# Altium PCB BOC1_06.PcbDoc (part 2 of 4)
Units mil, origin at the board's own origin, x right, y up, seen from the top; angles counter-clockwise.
Board outline 7900 x 6500 mil, 2 copper layers (Top Layer, Bottom Layer); 312 components, 413 nets, 1710 pads, 368 vias.
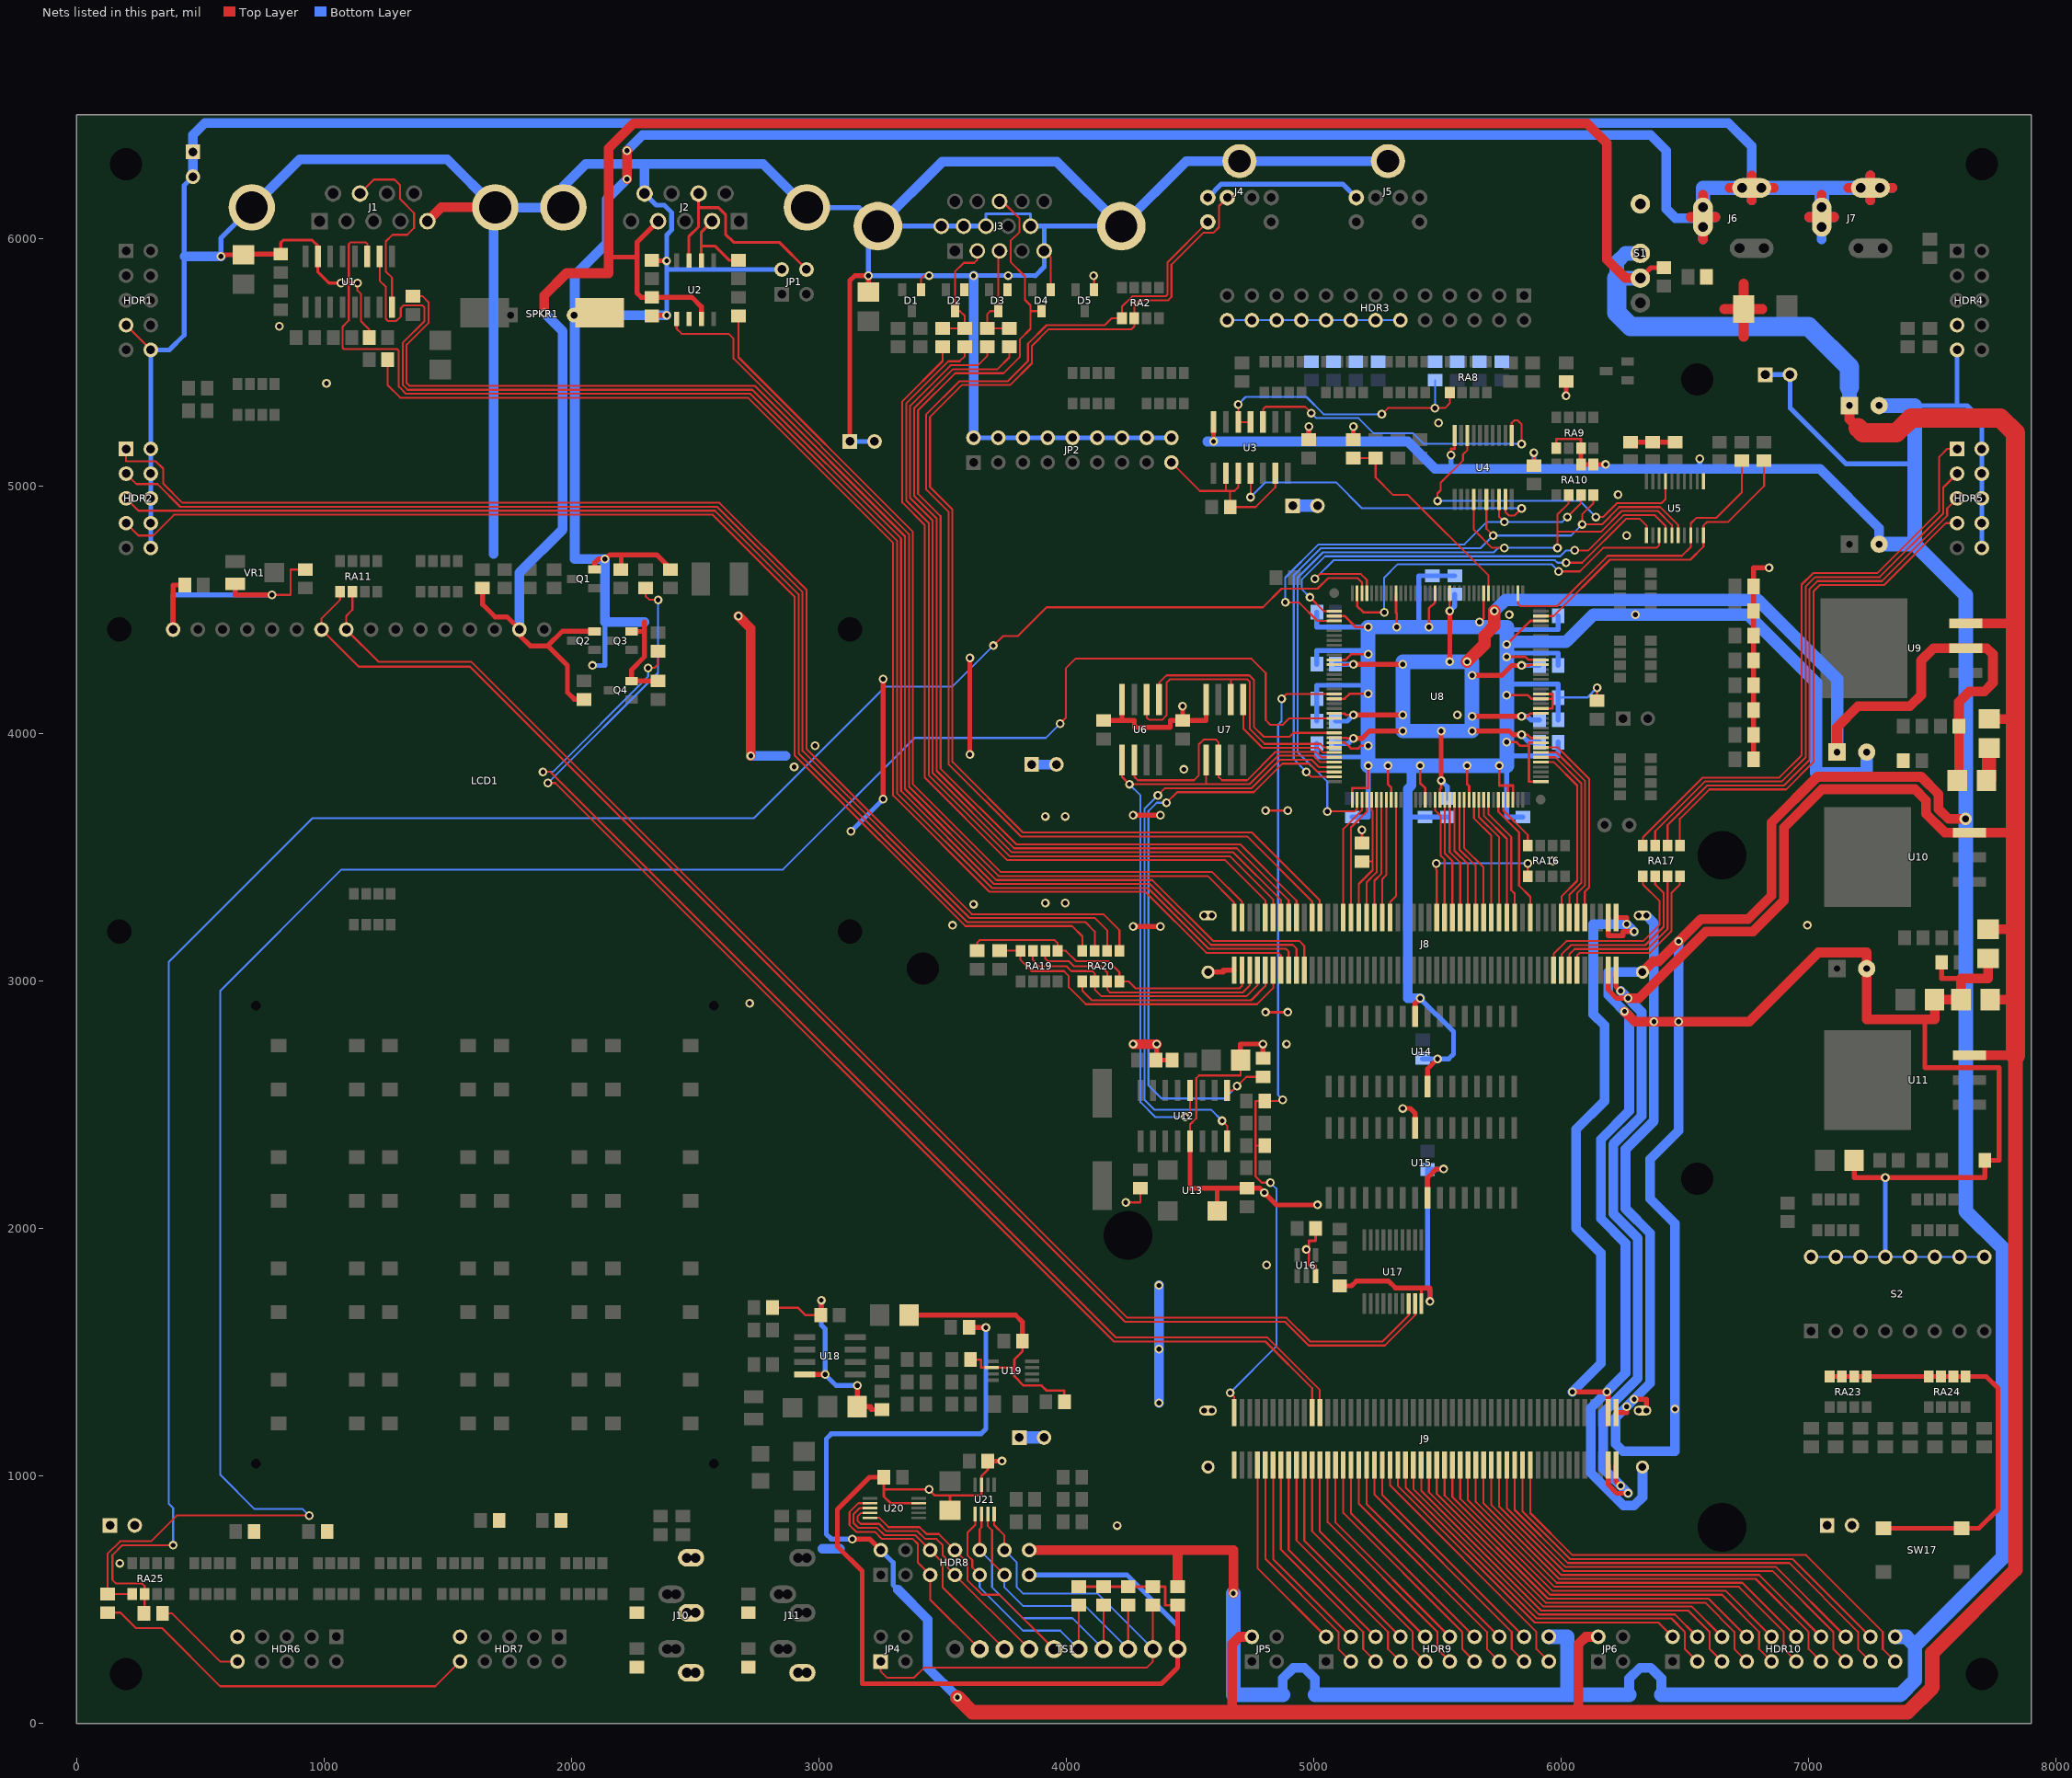
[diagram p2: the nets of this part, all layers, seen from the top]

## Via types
v1: diameter 35.43, hole 19.68, Top Layer to Bottom Layer, 194 vias
v2: diameter 35.43, hole 19.68, Top Layer to Bottom Layer, tented both sides, 169 vias
v3: diameter 50, hole 27.56, Top Layer to Bottom Layer, 5 vias

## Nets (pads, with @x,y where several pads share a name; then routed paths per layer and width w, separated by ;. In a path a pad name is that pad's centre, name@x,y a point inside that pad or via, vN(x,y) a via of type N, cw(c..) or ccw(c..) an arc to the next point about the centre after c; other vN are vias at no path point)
1V8: C21.1 C23.1 C58.1 C62.1 C63.1 C66.1 C67.1 C68.1 C69.1 C71.1 R42.1 U8.19 U8.46 U8.51 U8.61 U8.88 U8.120 U8.130 U8.135 U9.2 | length 7663.7
  Top Layer w9.84: U8.135@5082.68,3982.68 5132.32,3982.68 5135,3980 v1(5160,3980) ; U8.130@5082.68,4081.1 5123.9,4081.1 5130,4075 v1(5160,4075) ; U8.120@5082.68,4277.95 5132.95,4277.95 5135,4280 v1(5160,4280) ; U8.19@5509.84,3732.68 5509.84,3774.84 5515,3780 v1(5515,3810) ; v1@5549.21,4495.79 U8.88@5549.21,4567.32 ; v1(5840,3995) 5865,3995 5877.32,3982.68 U8.46@5917.32,3982.68 ; v1(5840,4070) 5865,4070 5876.1,4081.1 U8.51@5917.32,4081.1 ; v1(5840,4275) 5870,4275 5872.95,4277.95 U8.61@5917.32,4277.95
  Top Layer w19.68: v1(5160,3980) 5195,3980 5225,4010 v1(5360,4010) ; v1(5160,4075) v1(5360,4075) ; v1(5160,4280) v1(5360,4280) ; v1(5515,3810) v1(5515,4010) ; v1(5550,4290) v1(5550,4495) ; v1(5640,4010) 5790,4010 5805,3995 v1(5840,3995) ; v1(5640,4070) v1(5840,4070) ; v1(5640,4235) 5760,4235 5800,4275 v1(5840,4275)
  Top Layer w35.43: C23.1@7600.95,3810 7607.4,3816.46 R42.1@7607.4,4030
  Top Layer w39.37: C21.1@7115,3925 7115,4025 7200,4110 7410,4110 7455,4155 7455,4295 7505,4345 7720,4345 7745,4320 7745,4205 7710,4170 7650,4170 7607.4,4127.4 R42.1@7607.4,4030
  Top Layer w50: v1(5620,4290) 5690,4360 5690,4395 5730,4435 v1(5730,4495)
  Bottom Layer w19.68: C69.1@5087.4,3960 5140,3960 v1(5160,3980) ; C67.1@5087.4,4050 5135,4050 v1(5160,4075) ; C63.1@5087.4,4280 v1(5160,4280) ; v1(5515,3810) 5540,3785 C71.1@5540,3737.4 ; v1(5550,4495) 5570,4515 C58.1@5570,4562.6 ; v1(5840,3995) 5870,3965 C68.1@5912.6,3965 ; v1(5840,4070) 5862,4070 5877,4055 C66.1@5912.6,4055 ; v1(5840,4275) C62.1@5912.6,4275
  Bottom Layer w50: v1(5730,4495) 5775,4540 6795,4540 7115,4220 C21.1@7115,3925
  Bottom Layer w59.06: v1(5360,4010) 5360,4290 5640,4290 v1(5640,4010) v1(5360,4010)
5V: C4.1 C15.1 C22.1 C26.1 C27.1 HDR8.2 J2.4 J8.97 J8.99 J9.97 J9.99 JP5.2 JP6.2 LCD1.15 Q2.2 R5.1 R30.1 R38.1 R61.1 S1.1 S1.2 U2.3 U9.3 U10.3 U11.3 | length 29328.4
  Top Layer w19.68: R30.1@1641.48,4583.6 1641.48,4521.1 1691.57,4471 1740.43,4471 LCD1.15@1790.57,4420.86 ; LCD1.15@1791.54,4418.46 1791.54,4396.04 1833.57,4354 1904.57,4354 ; R38.1@2051.47,4138.6 2010.98,4138.6 1983.57,4166 1983.57,4275 1904.57,4354 ; Q2.2@2094.88,4413.4 1963.98,4413.4 1904.57,4354 ; 2150,5925 2265,5925 ; J2.4@2350.24,6070.08 2265,5984.84 2265,5780 2282.6,5762.4 2487.6,5762.4 2525,5725 U2.3@2525,5675 ; v1(3135,745) 3205,745 HDR8.2@3250,700 ; R61.1@3607.4,1600 v1(3675,1600) ; J9.97@6190.16,1043.7 6190.16,964.84 6225,930 v1(6270,930) ; J8.97@6190.16,3043.7 6190.16,2964.84 6225,2930 v1(6270,2930) ; J9.99@6221.65,1043.7 6221.65,978.35 v1(6240,960) ; J8.99@6221.65,3043.7 6221.65,2978.35 v1(6240,2960) ; S1.2@6320,5840 6362.4,5882.4 R5.1@6415,5882.4
  Top Layer w39.37: v2(1890,5700) 1890,5770 1980,5860 2150,5860 2150,6365 2250,6465 6105,6465 6185,6385 6185,5915 6260,5840 S1.2@6320,5840 ; 4670,45 4670,320 4700,350 JP5.2@4750,350 ; 6070,45 6070,320 6100,350 JP6.2@6150,350 ; v1(6270,2930) 6315,2930 6585,3200 6775,3200 6900,3325 6900,3620 7055,3775 7430,3775 7475,3730 7475,3675 7550,3600 7836,3600 ; C15.1@7165,5325 7165,5270 7200,5235 ; U9.3@7635,4445 7836,4445 ; U11.3@7650,2700 7836,2700 ; C27.1@7725,3209.05 7836,3209.05 ; C22.1@7730,4059.05 7836,4059.05 ; C26.1@7734.05,2925 7836,2925
  Top Layer w59.06: v1(3560,105) 3620,45 7400,45 7500,145 7500,285 7836,621 7836,2700
  Top Layer w78.74: 7200,5235 7220,5215 7355,5215 7415,5275 7775,5275 7836,5214 7836,2700
  Bottom Layer w19.68: v1(3135,745) 3050,745 3030,765 3030,1150 3050,1170 3655,1170 3675,1190 v1(3675,1600) ; HDR8.2@3250,700 3300,650 3300,560 3320,540
  Bottom Layer w39.37: LCD1.15@1790,4420 1790,4650 1965,4825 1965,5625 v2(1890,5700) ; 3320,540 3440,420 3440,225 v1(3560,105) ; v1(6240,2960) 6325,2875 6325,2455 6210,2340 6210,2060 6310,1960 6310,1395 6170,1255 6170,1030 v1(6270,930)
  Bottom Layer w59.06: S1.2@6320,5840 6225,5840 6225,5905 6260,5940 S1.1@6320,5940 ; C15.1@7165,5325 7165,5400
  Bottom Layer w78.74: 6225,5840 6225,5700 6280,5645 7000,5645 7165,5480 7165,5400
AGND: C36.2 C37.1 C38.2 C39.2 C41.2 C42.2 C44.2 C47.2 C48.2 C49.2 C50.2 C51.2 C52.2 C53.2 C54.2 C55.2 C56.2 C57.2 HDR8.13 J10.1 J10.1A J10.1B J10.3 J10.3A J10.3B J10.5 J10.5A J10.5B J11.1 J11.1A J11.1B R65.1 R80.2 TS1.10 U18.4 U19.2 U20.4 U21.7 | length 6959.1
  Top Layer w9.84: C36.2@2812.4,1680 2915,1680 2945,1650 C37.1@3010,1650 ; 3262.6,945 v1(3445,945) 3469,921 3657.2,921 3657.2,999.2 3682.4,1024.4 C49.2@3682.4,1060 ; C47.2@3262.6,995 3262.6,917.4 3290.32,889.68 U20.4@3403.43,889.68 ; C48.2@3530,860.94 3530,921 ; C41.2@3612.4,1470 3655,1470 3655,1437.8 3790,1437.8 ; C42.2@3822.4,1545 3822.4,1502.4 3790,1470 3790,1403 3828,1365 3900,1365 3920,1345 3992.4,1345 C44.2@3992.4,1300 ; C54.2@4050,552.4 4400,552.4 4400,477.6 R80.2@4450,477.6
  Top Layer w19.68: U18.4@2942.64,1410 v1(3025,1410) ; C37.1@3010,1650 v1(3010,1710) ; v1(3155,1365) 3155,1280 3210,1280 3210,1267.6 R65.1@3255,1267.6 ; C47.2@3260.78,995 C47.2@3262.6,995 3205,995 3075,865 3075,715 3175,615 3175,160 4385,160 4450,225 R80.2@4450,477.6 ; C38.2@3364.06,1650 3795,1650 3822.4,1622.6 C42.2@3822.4,1545 ; C49.2@3682.4,1060 v1(3740,1060)
  Bottom Layer w19.68: v1(3010,1710) 3010,1610 3025,1595 v1(3025,1410) 3070,1365 v1(3155,1365) ; HDR8.13@3850,600 4245,600 4450,395 TS1.10@4450,300
  Bottom Layer w39.37: 3015,705 3085,705
AIN0: C54.1 HDR8.9 TS1.6 U21.1 | length 1010.9
  Top Layer w7.87: U21.1@3631.61,845.94 3631.61,801.61 3600,770 3600,680 3620,660 3620,630 HDR8.9@3650,600 ; TS1.6@4050,300 C54.1@4050,477.6
  Bottom Layer w7.87: HDR8.9@3650,600 3650,550 3825,375 3975,375 TS1.6@4050,300
AIN1: C55.1 HDR8.10 TS1.7 U21.2 | length 1050.8
  Top Layer w7.87: HDR8.10@3650,700 3650,785 3657.2,792.2 U21.2@3657.2,845.94 ; TS1.7@4150,300 C55.1@4150,477.6
  Bottom Layer w7.87: HDR8.10@3650,700 3700,650 3700,550 3825,425 4025,425 TS1.7@4150,300
AIN2: C56.1 HDR8.11 TS1.8 U21.3 | length 1104.9
  Top Layer w7.87: U21.3@3682.8,845.94 3682.8,797.2 3700,780 3700,650 HDR8.11@3750,600 ; TS1.8@4250,300 C56.1@4250,477.6
  Bottom Layer w7.87: HDR8.11@3750,600 3750,550 3825,475 4075,475 TS1.8@4250,300
AIN3: C57.1 HDR8.12 JP4.1 TS1.9 U21.4 | length 2392.3
  Top Layer w7.87: JP4.1@3250,250 3250,210 3275,185 3385,185 3425,225 4325,225 4350,250 C57.1@4350,477.6 ; U21.4@3708.39,845.94 3708.39,801.61 3750,760 HDR8.12@3750,700
  Bottom Layer w7.87: HDR8.12@3750,700 3800,650 3800,550 3825,525 4125,525 TS1.9@4350,300
AOUT0: HDR8.5 TS1.2 U20.7 | length 986.4
  Top Layer w7.87: U20.7@3206.57,889.68 3159.68,889.68 3124,854 3124,801 3151,774 3226,774 3255,745 3380,745 3400,725 3400,650 HDR8.5@3450,600 3450,500 TS1.2@3650,300
AOUT1: HDR8.6 TS1.3 U20.8 | length 991.8
  Top Layer w7.87: U20.8@3206.57,870 3165,870 3140,845 3140,810 3160,790 3235,790 3264,761 3389,761 3500,650 3500,550 TS1.3@3750,300
AOUT2: HDR8.7 TS1.4 U20.9 | length 1023.5
  Top Layer w7.87: U20.9@3206.57,850.31 3170.31,850.31 3156,836 3156,819 3169,806 3244,806 3273,777 3398,777 3430,745 3475,745 3500,720 3500,680 3520,660 3520,630 TS1.4@3850,300
AOUT3: HDR8.8 TS1.5 U20.10 | length 1004.2
  Top Layer w7.87: U20.10@3206.57,830.63 3244.37,830.63 3282,793 3407,793 3435,765 3485,765 3600,650 3600,580 3660,520 3730,520 TS1.5@3950,300
AUDIO_SPI_CSN: J8.11 R46.1 RA19.8 | length 1343.1
  Top Layer w7.87: R46.1@3730,3122 RA19.8@3815,3122 3815,3085 3860,3040 3990,3040 4010,3020 4010,2975 4079,2906 4771,2906 4835.83,2970.83 J8.11@4835.83,3043.7
BLUE0: J8.14 R14.1 | length 3644.5
  Top Layer w7.87: R14.1@3680,5562.6 3680,5525 3643,5488 3533,5488 3369,5324 3369,4951 3460,4860 3460,3840 3780,3520 4675,3520 4867.32,3327.68 J8.14@4867.32,3256.3
BLUE1: J8.16 R15.1 | length 3725.5
  Top Layer w7.87: R15.1@3770,5562.6 3770,5520 3722,5472 3542,5472 3385,5315 3385,4960 3476,4869 3476,3849 3789,3536 4689,3536 4898.82,3326.18 J8.16@4898.82,3256.3
BLUE#: D3.3 J3.3 R14.2 R15.2 | length 442.4
  Top Layer w7.87: R14.2@3679.9,5637.4 R15.2@3769.9,5637.4 ; R14.2@3680,5637.4 3679.9,5693.9 3692.69,5706.69 D3.3@3725,5706.69 3725,5944.68 J3.3@3730.32,5950
BOC_CTS: J8.13 R9.1 | length 5324.1
  Top Layer w7.87: R9.1@1257.4,5510 1257.4,5407.6 1308,5357 2713,5357 3300,4770 3300,3750 3690,3360 4320,3360 4566,3114 4857,3114 4867.32,3103.68 J8.13@4867.32,3043.7
BOC_EN: U3.11 U4.19 | length 1394.9
  Top Layer w7.87: v2(4745,4955) U3.11@4745,5051.65 ; U4.19@5774.57,4946.06 5774.57,4895.43 5790,4880 5810,4880 v2(5840,4910)
  Bottom Layer w7.87: v2(4745,4955) 4805,5015 5090,5015 5195,4910 v2(5840,4910)
BOC_RTS: J8.17 U1.10 | length 6060.7
  Top Layer w7.87: U1.10@1225,5927.36 1225,5830 1250,5805 1250,5675 1258,5667 1292,5667 1310,5685 1310,5719 1321,5730 1397,5730 1406,5721 1406,5666 1318,5578 1318,5409 1338,5389 2731,5389 3332,4788 3332,3768 3708,3392 4338,3392 4584,3146 4915,3146 4930.31,3130.69 J8.17@4930.31,3043.7
BOC_RX: J8.19 R1.1 | length 5700.6
  Top Layer w7.87: R1.1@1360,5767.4 1397.6,5767.4 1422,5743 1422,5659 1334,5571 1334,5416 1345,5405 2740,5405 3348,4797 3348,3777 3717,3408 4347,3408 4593,3162 4941,3162 4961.81,3141.19 J8.19@4961.81,3043.7
BOC_TX: J8.15 U1.11 | length 6152.7
  Top Layer w7.87: U1.11@1175,5927.36 1175,5978 1169,5984 1106.27,5984 1100,5977.73 1100,5669 1075,5644 1075,5558 1080,5553 1296,5553 1302.25,5546.75 1302.25,5401.75 1331,5373 2722,5373 3316,4779 3316,3759 3699,3376 4329,3376 4575,3130 4888,3130 4898.82,3119.18 J8.15@4898.82,3043.7
BOOT_EN: U3.3 U4.1 | length 1344.3
  Top Layer w7.87: U3.3@4795,5258.35 4795,5310 4805,5320 4965,5320 v2(4990,5295) ; U4.1@5800.16,5203.94 5800.16,5255.16 5810,5265 5825,5265 5840,5250 v2(5840,5170)
  Bottom Layer w7.87: v2(4990,5295) 5011,5274 5181,5274 5242,5213 5402,5213 5445,5170 v2(5840,5170)
BOOT_JTAG_EN: JP2.17 R28.1 U3.9 U3.10 U3.13 | length 789.5
  Top Layer w7.87: JP2.17@4425,5095 4540,4980 4680,4980 4695,4995 U3.10@4695,5051.65 ; 4645,4980 U3.9@4645,5051.65 ; 4662.4,4980 R28.1@4662.4,4915 4765,4915 4845,4995 U3.13@4845,5051.65
BOOT_TCK: RA10.4 U4.16 U5.6 U8.143 | length 2969.7
  Top Layer w7.87: v1(4970,3845) 4989.8,3825.2 U8.143@5082.68,3825.2 ; U4.16@5697.8,4946.06 5697.8,4827.2 v2(5725,4800) ; RA10.4@6130,4963 6130,4930 6085,4885 v2(6085,4845) 6165,4845 6235,4915 6400,4915 6472.8,4842.2 U5.6@6472.8,4800.75
  Bottom Layer w7.87: v1(4970,3845) 4919,3896 4919,4639 5028,4748 5673,4748 v2(5725,4800) 6040,4800 v2(6085,4845)
BOOT_TDI: RA10.3 U4.18 U8.111 | length 1780.7
  Top Layer w7.87: v1(4885,4530) 4940,4530 5014.88,4455.12 U8.111@5082.68,4455.12 ; U4.18@5748.98,4946.06 5748.98,4876.02 v2(5770,4855) ; v2(6025,4875) 6080,4930 RA10.3@6080,4963
  Bottom Layer w7.87: v1(4885,4530) 4885,4630 5019,4764 5609,4764 5700,4855 6005,4855 v2(6025,4875)
BOOT_TDO: U4.8 U5.17 | length 1364.9
  Top Layer w7.87: v2(5500,4940) 5500,4970 5513,4983 5513,5013 5603,5103 5603,5128 5621.02,5146.02 U4.8@5621.02,5203.94 ; v2(6140,4875) 6170,4875 6226,4931 6406,4931 6421.61,4946.61 U5.17@6421.61,5019.25
  Bottom Layer w7.87: v2(5500,4940) 6075,4940 v2(6140,4875)
BOOT_TDO-TDI: U5.4 U8.109 | length 1841
  Top Layer w7.87: v1(4985,4550) 5040.51,4494.49 U8.109@5082.68,4494.49 ; v1(6055,4740) 6110,4740 6253,4883 6377,4883 6421.61,4838.39 U5.4@6421.61,4800.75
  Bottom Layer w7.87: v1(4985,4550) 4951,4584 4951,4621 5046,4716 5996,4716 6020,4740 v1(6055,4740)
BOOT_TMS: RA10.2 U4.14 U5.5 U8.2 | length 3326.7
  Top Layer w7.87: v1(5055,3685) 5165,3685 5175.2,3695.2 U8.2@5175.2,3732.68 ; U4.14@5646.61,4946.06 5646.61,4823.39 5720,4750 v1(5770,4750) ; v1(5985,4750) 5985,4885 6030,4930 RA10.2@6030,4963 ; 5985,4815 6160,4815 6244,4899 6391,4899 6447.2,4842.8 U5.5@6447.2,4800.75
  Bottom Layer w7.87: v1(5055,3685) 5055,3805 4935,3925 4935,4630 5037,4732 5727,4732 5745,4750 v1(5985,4750)
BUZZER: J9.24 R37.1 | length 4983.6
  Top Layer w7.87: v2(1885,3845) 1915,3845 4201,1559 4813,1559 5024.8,1347.2 J9.24@5024.8,1256.3 ; v2(2310,4265) 2335,4265 2350,4280 R37.1@2350,4332.6
  Bottom Layer w7.87: v2(1885,3845) 1925,3845 2310,4230 v2(2310,4265)
C_CTRL: C76.1 R22.2 U8.80 | length 859.6
  Top Layer w7.87: C76.1@5160,5112.6 R22.2@5250,5112.6 5250,5035 5321,4964 5381,4964 5706.69,4638.31 U8.80@5706.69,4567.32
C_SPI_CLK: U6.6 U7.6 U8.139 | length 1229.3
  Top Layer w7.87: U6.6@4275,3892.95 4275,3825 4289,3811 4516,3811 4535,3830 4535,3955 4555,3975 4605,3975 4615,3965 4615,3825 4629,3811 4731,3811 4846,3926 5009,3926 5031.06,3903.94 U8.139@5082.68,3903.94
C_SPI_CLOCK_CLK: U8.141 U12.8 | length 2477.3
  Top Layer w7.87: v1(4370,3750) 4399,3779 4749,3779 4864,3894 4991,3894 5020.43,3864.57 U8.141@5082.68,3864.57 ; v2(4630,2435) 4650,2415 U12.8@4650,2352.64
  Bottom Layer w7.87: v1(4370,3750) 4316,3696 4316,2519 4355,2480 4585,2480 v2(4630,2435)
C_SPI_CLOCK_SEL: R50.1 U8.142 U12.9 | length 2521.1
  Top Layer w7.87: v1(4405,3720) 4448,3763 4758,3763 4873,3878 4982,3878 5015.12,3844.88 U8.142@5082.68,3844.88 ; U12.9@4650,2557.36 4672.36,2557.36 4727.6,2612.6 R50.1@4795,2612.6
  Bottom Layer w7.87: v1(4405,3720) 4365,3720 4332,3687 4332,2578 4385,2525 4640,2525 v1(4690,2575)
C_SPI_DIN: U6.5 U7.5 U8.140 U12.12 | length 2718.4
  Top Layer w7.87: U6.5@4225,3892.95 4225,3825 v1(4255,3795) 4740,3795 4855,3910 5000,3910 5025.75,3884.25 U8.140@5082.68,3884.25 ; v2(4480,2450) 4500,2470 U12.12@4500,2557.36 ; 4565,3795 U7.5@4565,3892.95
  Bottom Layer w7.87: v1(4255,3795) 4300,3750 4300,2510 4360,2450 v2(4480,2450)
C_SPI_DOUT: U6.2 U7.2 U8.137 | length 1286.6
  Top Layer w7.87: U6.2@4325,4137.05 4325,4065 4335,4055 4387,4055 4405,4073 4405,4205 4419,4219 4731,4219 4742,4208 4742,4018 4802,3958 5027,3958 5041.69,3943.31 U8.137@5082.68,3943.31 ; U7.2@4665,4137.05 4665,4219
C_SPI_SEL_FLSH1: U7.1 U8.138 | length 524.6
  Top Layer w7.87: U7.1@4715,4137.05 4715,4020 4793,3942 5018,3942 5036.38,3923.62 U8.138@5082.68,3923.62
C_SPI_SEL_FLSH2: U6.1 U8.134 | length 1008.4
  Top Layer w7.87: U6.1@4375,4137.05 4375,4205 4405,4235 4740,4235 4758,4217 4758,4027 4798,3987 4902,3987 4917.36,4002.36 U8.134@5082.68,4002.36
CAN_RXD: J8.4 R4.1 | length 3775
  Top Layer w7.87: R4.1@2675,5687.6 2675,5520 3380,4815 3380,3795 3735,3440 4590,3440 4709.84,3320.16 J8.4@4709.84,3256.3
CAN_TXD: J8.2 U2.1 | length 3958.4
  Top Layer w7.87: U2.1@2425,5675 2425,5635 2445,5615 2635,5615 2655,5595 2655,5515 3364,4806 3364,3786 3726,3424 4571,3424 4678.35,3316.65 J8.2@4678.35,3256.3
CANH: J2.7 JP1.4 U2.7 | length 872.3
  Top Layer w11.81: U2.7@2475,5911.22 2475,6009 2513.83,6047.83 J2.7@2513.83,6180.89 ; 2513.83,6125 2595,6125 2622.88,6097.12 2622.88,6017.12 2655,5985 2840,5985 JP1.4@2950,5875
CANL: J2.2 R3.2 U2.6 | length 349.7
  Top Layer w11.81: U2.6@2525,5911.22 2525,6025.73 J2.2@2568.35,6069.08 ; 2525,5970 2579,5970 2636.6,5912.4 R3.2@2675,5912.4
CCLK: U5.3 U8.107 | length 1541.6
  Top Layer w7.87: v1(5990,4655) 6075,4655 6170,4750 6385,4750 6396.02,4761.02 U5.3@6396.02,4800.75
  Top Layer w9.84: U8.107@5175.2,4567.32 5175.2,4514.8 5200,4490 v2(5285,4490)
  Bottom Layer w7.87: v2(5285,4490) 5285,4630 5339,4684 5961,4684 v1(5990,4655)
CTRL: C84.1 RA8.1 U3.4 U3.5 | length 1192.3
  Top Layer w7.87: v2(4695,5330) U3.5@4695,5258.35 U3.4@4745,5258.35 ; v2(5275,5290) 5300,5315 5530,5315 5550,5335 RA8.1@5550,5378
  Bottom Layer w7.87: v2(4695,5330) 4725,5360 4970,5360 5040,5290 v2(5275,5290) ; v2(5490,5315) C84.1@5490,5427.6
CTS: J1.7 U1.8 | length 803
  Top Layer w7.87: J1.7@1145.47,6181.89 1201.58,6238 1285,6238 1308,6215 1308,6159 1364,6103 1364,6043 1336,6015 1277,6015 1250,5988 1250,5867 1275,5842 U1.8@1275,5722.64
DIN: U5.1 U8.105 | length 1779.2
  Top Layer w7.87: v2(5005,4625) 5024,4644 5191,4644 5214.57,4620.43 U8.105@5214.57,4567.32 ; v1(6020,4690) 6085,4690 6262,4867 6318,4867 6344.84,4840.16 U5.1@6344.84,4800.75
  Bottom Layer w7.87: v2(5005,4625) 5080,4700 5975,4700 5985,4690 v1(6020,4690)
DONE: R27.2 U5.10 U8.71 | length 1270.3
  Top Layer w7.87: U8.71@5917.32,4474.8 5969.8,4474.8 6197,4702 6522,4702 6575.16,4755.16 6575.16,4840.16 6589,4854 6674,4854 6820.16,5000.16 R27.2@6820,5100.2
FPGA_AUX0: J8.86 U8.41 | length 746.9
  Top Layer w7.87: U8.41@5917.32,3884.25 5970.75,3884.25 6065,3790 6065,3405 6001.18,3341.18 J8.86@6001.18,3256.3
FPGA_AUX1: J8.88 U8.42 | length 769.9
  Top Layer w7.87: U8.42@5917.32,3903.94 5976.06,3903.94 6081,3799 6081,3396 6032.68,3347.68 J8.88@6032.68,3256.3
FPGA_AUX2: J8.90 U8.43 | length 792.9
  Top Layer w7.87: U8.43@5917.32,3923.62 5981.38,3923.62 6097,3808 6097,3387 6064.17,3354.17 J8.90@6064.17,3256.3
FPGA_AUX3: J8.92 U8.44 | length 815.9
  Top Layer w7.87: U8.44@5917.32,3943.31 5986.69,3943.31 6113,3817 6113,3378 6095.67,3360.67 J8.92@6095.67,3256.3
FPGA_CCLK: J8.66 U8.24 | length 508.7
  Top Layer w7.87: U8.24@5608.27,3732.68 5608.27,3536.73 5686.22,3458.78 J8.66@5686.22,3256.3
FPGA_CLK: J9.2 R51.2 R53.2 U8.126 | length 3402.3
  Top Layer w7.87: v1(4662,1336) 4678.35,1319.65 J9.2@4678.35,1256.3 ; 4765,2335 R53.2@4802.4,2335 ; v2(4825,2185) 4790,2185 4765,2210 4765,2515 4870,2515 v1(4875,2520) ; v1(4870,4140) 4889.84,4159.84 U8.126@5082.68,4159.84
  Bottom Layer w7.87: v1(4662,1336) 4849,1523 4849,2161 v2(4825,2185) ; v1(4870,4140) 4870,4050 4856,4036 4856,2539 v1(4875,2520)
FPGA_CLK_1: J8.30 U8.3 | length 507.7
  Top Layer w7.87: J8.30@5119.29,3256.3 5119.29,3614.29 5194.88,3689.88 U8.3@5194.88,3732.68
FPGA_CLK_2: J8.32 U8.4 | length 502.8
  Top Layer w7.87: J8.32@5150.79,3256.3 5150.79,3620.79 5214.57,3684.57 U8.4@5214.57,3732.68
FPGA_DIN: J8.64 U8.23 | length 503.8
  Top Layer w7.87: U8.23@5588.58,3732.68 5588.58,3531.42 5654.72,3465.28 J8.64@5654.72,3256.3
FPGA_DONE: J8.74 U8.29 | length 520.1
  Top Layer w7.87: U8.29@5706.69,3732.68 5706.69,3673.31 5798,3582 5798,3367 5812.21,3352.79 J8.74@5812.21,3256.3
FPGA_ID0: J8.42 U8.10 | length 486.5
  Top Layer w7.87: J8.42@5308.27,3256.3 5308.27,3318.27 5332.68,3342.68 U8.10@5332.68,3732.68
FPGA_ID1: J8.40 U8.8 | length 483.2
  Top Layer w7.87: J8.40@5276.77,3256.3 5276.77,3411.77 5293.31,3428.31 U8.8@5293.31,3732.68
FPGA_ID2: J8.38 U8.7 | length 488.1
  Top Layer w7.87: J8.38@5245.28,3256.3 5245.28,3405.28 5273.62,3433.62 U8.7@5273.62,3732.68
FPGA_ID3: J8.36 U8.6 | length 493
  Top Layer w7.87: J8.36@5213.78,3256.3 5213.78,3398.78 5253.94,3438.94 U8.6@5253.94,3732.68
FPGA_INIT: J8.68 U8.26 | length 505.4
  Top Layer w7.87: U8.26@5647.64,3732.68 5647.64,3657.36 5717.72,3587.28 J8.68@5717.72,3256.3
FPGA_INSTALLED: J8.34 R44.2 U8.5 | length 544
  Top Layer w7.87: J8.34@5182.28,3256.3 5182.28,3392.28 5238,3448 5238,3687 5234.25,3690.75 U8.5@5234.25,3732.68 ; R44.2@5195,3482.6 5238,3482.6
FPGA_M0: J8.60 U8.21 | length 494
  Top Layer w7.87: U8.21@5549.21,3732.68 5549.21,3520.79 5591.73,3478.27 J8.60@5591.73,3256.3
FPGA_M1: J8.58 U8.20 | length 489.1
  Top Layer w7.87: U8.20@5529.53,3732.68 5529.53,3515.47 5560.24,3484.76 J8.58@5560.24,3256.3
FPGA_M2: J8.56 U8.18 | length 492.4
  Top Layer w7.87: U8.18@5490.16,3732.68 5490.16,3689.84 5513,3667 5513,3507 5528.74,3491.26 J8.56@5528.74,3256.3
FPGA_PROGRAM: J8.62 U8.22 | length 498.9
  Top Layer w7.87: U8.22@5568.9,3732.68 5568.9,3526.1 5623.23,3471.77 J8.62@5623.23,3256.3
FPGA_TCK: J8.72 U8.28 | length 515.2
  Top Layer w7.87: U8.28@5687.01,3732.68 5687.01,3667.99 5780.71,3574.29 J8.72@5780.71,3256.3
FPGA_TDI: J8.78 U8.31 | length 529.9
  Top Layer w7.87: U8.31@5746.06,3732.68 5746.06,3683.94 5830,3600 5830,3385 5875.2,3339.8 J8.78@5875.2,3256.3
FPGA_TDO: J8.54 RA16.1 | length 641.6
  Top Layer w7.87: v1(5495,3475) 5495,3450 5497.24,3447.76 J8.54@5497.24,3256.3 ; RA16.1@5865,3423 v1(5865,3475)
  Bottom Layer w7.87: v1(5495,3475) v1(5865,3475)
FPGA_TDO#: RA16.8 U8.32 | length 226.8
  Top Layer w7.87: U8.32@5765.75,3732.68 5765.75,3689.25 5865,3590 RA16.8@5865,3547
FPGA_TMS: J8.70 U8.27 | length 510.3
  Top Layer w7.87: U8.27@5667.32,3732.68 5667.32,3662.68 5749.21,3580.79 J8.70@5749.21,3256.3
GND: C1.2 C2.2 C4.2 C5.2 C8.2 C10.2 C11.2 C12.1 C13.1 C14.1 C15.2 C16.2 C17.2 C18.2 C19.1 C20.2 C21.2 C22.2 C23.2 C24.2 C25.2 C26.2 C27.2 C28.2 C29.2 C30.2 C31.2 C32.2 C33.2 C34.2 C35.2 C58.2 C59.2 C60.2 C61.2 C62.2 C63.2 C64.2 C65.2 C66.2 C67.2 C68.2 C69.2 C70.2 C71.2 C72.2 C73.2 C74.2 C75.2 C76.2 C77.2 C78.2 C79.2 C80.2 C81.2 C82.2 C83.2 C84.2 C85.2 C86.2 C87.2 C88.2 D1.1 D2.1 D3.1 D4.1 D5.1 D7.1 GJ1.1 GJ1.2 GJ2.1 GJ2.2 GJ3.1 GJ3.2 GJ4.1 GJ4.2 GJ5.1 GJ5.2 GJ6.1 GJ6.2 GJ7.1 GJ7.2 GJ8.1 GJ8.2 HDR1.7 HDR1.10 HDR2.2 HDR2.4 HDR2.6 HDR2.8 HDR2.10 HDR3.19 HDR3.20 HDR3.21 HDR3.22 HDR3.23 HDR3.24 HDR3.25 HDR3.26 HDR4.7 HDR4.9 HDR5.2 HDR5.4 HDR5.6 HDR5.8 HDR5.10 HDR6.9 HDR7.9 HDR8.14 HDR9.20 HDR10.20 J1.5 J1.10 J1.11 J2.9 J2.10 J2.11 J3.5 J3.6 J3.7 J3.8 J3.10 J3.16 J3.17 J4.3 J4.S J5.3 J5.S J6.2 J6.2A J6.2B J6.3 J6.3A J6.3B J7.2 J7.2A J7.2B J7.3 J7.3A J7.3B J8.1 J8.98 J8.100 J8.MH1 J8.MH2 J8.MH2A J8.MH2B J8.MH3 J8.MH4 J8.MH4A J8.MH4B J9.1 J9.98 J9.100 J9.MH1 J9.MH2 J9.MH2A J9.MH2B J9.MH3 J9.MH4 J9.MH4A J9.MH4B JP1.2 JP2.2 JP2.4 JP2.6 JP2.8 JP2.10 JP2.12 JP2.14 JP2.16 JP2.18 LCD1.1 LED8.2 LED9.2 LED10.2 LED11.2 LED12.2 LED13.2 LED14.2 LED15.2 LED16.2 Q1.2 Q3.2 Q4.2 R2.1 R19.2 R29.2 R34.1 R39.2 R40.1 R43.2 R44.1 R49.1 R50.2 R58.2 R80.1 RA9.1 RA9.3 RA10.5 RA10.6 RA23.5 RA23.6 RA23.7 RA23.8 RA24.5 RA24.6 RA24.7 RA24.8 S1.M S2.9 S2.10 S2.11 S2.12 S2.13 S2.14 S2.15 S2.16 SPKR1.2 SPKR1.2A SW17.3 SW17.4 U1.15 U2.2 U3.7 U4.10 U5.11 U6.4 U7.4 U8.1 U8.9 U8.16 U8.25 U8.33 U8.34 U8.37 U8.45 U8.52 U8.54 U8.55 U8.62 U8.70 U8.81 U8.91 U8.99 U8.110 U8.119 U8.127 U8.136 U12.5 U13.2 U14.9 U14.25 U15.9 U15.25 U16.3 U17.10 VR1.CCW | length 92487.9
  Top Layer w7.87: HDR1.7@200,5650 HDR1.10@300,5550 ; v2(790,4560) 865,4560 865,4662.4 R29.2@925,4662.4 ; v2(1135,5820) 1135,5790 1149.8,5775.2 1149.8,5665 1182.6,5632.2 C8.2@1182.6,5600 ; D1.1@3412.4,5793.31 3412.4,5837.4 3425.39,5850.39 v1(3445,5850.39) ; J3.5@3910.63,5950 3937.4,5923.23 D4.1@3937.4,5793.31 ; v2(4110,5850) 4112.4,5847.6 D5.1@4112.4,5793.31 ; v2(4240,2105) 4300,2105 C31.2@4300,2162.6 ; U12.5@4500,2352.64 4500,2420 4525,2445 4525,2607 4536,2618 4704.06,2618 C30.2@4704.06,2680
  Top Layer w9.84: v1(4805,2873.68) v1(4895,2873.68) ; v1(4805,3688.57) v1(4895,3688.57) ; U16.3@5007.4,1807.68 5007.4,1850 4980,1850 4980,1950 5007.4,1950 C33.2@5007.4,2000 ; U8.136@5082.68,3962.99 5127.01,3962.99 5150,3940 5180,3940 5190,3950 v1(5220,3950) ; U8.127@5082.68,4140.16 5125.16,4140.16 5145,4160 v1(5220,4160) ; U8.119@5082.68,4297.64 5127.64,4297.64 5150,4320 v1(5220,4320) ; U8.110@5082.68,4474.8 5125.2,4474.8 5170,4430 v1(5220,4430) ; U8.1@5155.51,3732.68 5155.51,3780 5220,3780 v1(5220,3870) ; R44.1@5195,3557.4 v1(5195,3610) ; v1(5300,3870) 5300,3795 5312.99,3782.01 U8.9@5312.99,3732.68 ; U8.99@5332.68,4567.32 5332.68,4487.32 5335,4485 v1(5335,4430) ; v1(5430,3870) 5430,3800 5450.79,3779.21 U8.16@5450.79,3732.68 ; v1(5465,4430) 5465,4505 5490.16,4530.16 U8.91@5490.16,4567.32 ; v2(5555,5125) 5555,5150 5569.84,5150 U4.10@5569.84,5203.94 ; v1(5620,3870) 5620,3795 5627.95,3787.05 U8.25@5627.95,3732.68 ; v1(5670,4450) 5687.01,4467.01 U8.81@5687.01,4567.32 ; v1(5750,3870) 5750,3790 5805.12,3790 U8.34@5805.12,3732.68 ; v1(5780,3965) 5820,3965 5835,3950 5870,3950 ; v1(5780,4155) 5865,4155 5879.84,4140.16 5965,4140.16 ; v1(5780,4310) 5855,4310 5867.36,4297.64 U8.62@5917.32,4297.64 ; v1(5780,4360) 5875.12,4455.12 U8.70@5917.32,4455.12 ; U8.33@5785.43,3732.68 5785.43,3790 ; C11.2@5890,5082.4 v1(5890,5135) ; U8.37@5917.32,3805.51 5870,3805.51 5870,3962.99 U8.45@5917.32,3962.99 ; U8.52@5917.32,4100.79 5965,4100.79 5965,4159.84 U8.55@5917.32,4159.84 ; RA9.1@5980,5153 5980,5190 6080,5190 RA9.3@6080,5153 ; R40.1@6145,4132.4 v1(6145,4185)
  Top Layer w11.81: C2.2@825,5937.4 824.9,5982.9 836,5994 952,5994 975,5971 975,5865 1020,5820 v2(1069,5820) ; U17.10@5435.16,1696.06 5435.16,1760
  Top Layer w19.68: LCD1.1@390,4420 390,4600 C17.2@437.6,4600 ; v2(583,5928) 589.06,5934.06 C1.2@675,5934.06 675,5937.4 C2.2@825,5937.4 ; VR1.CCW@641,4598 641,4560 v2(790,4560) ; Q1.2@2094.88,4663.4 2094.88,4691.31 2109.57,4706 2138.57,4706 2154.57,4722 2344.57,4722 C18.2@2401.48,4665.1 ; 2201.57,4722 2201.57,4663.5 R34.1@2201.67,4663.4 ; Q3.2@2243.31,4412.4 2295,4412.4 ; 2295,4450 2295,4310 2243.31,4258.31 Q4.2@2243.31,4212.4 R39.2@2350,4212.4 ; C4.2@2340,5690 v2(2385,5690) ; R2.1@2340,5910 v2(2385,5910) ; GJ2.1@3125,5180 3125,5830 3145,5850 v2(3200,5850) C5.2@3200,5784.06 ; v2(3260,3735) v2(3260,4220) ; v2(3610,3915) v2(3610,4305) ; C19.1@4150,4052.4 4275,4052.4 4275,4025 4420,4025 4420,4052.4 4565,4052.4 U7.4@4565,4137.05 ; 4225,4052.4 U6.4@4225,4137.05 ; v2(4270,3220) v2(4380,3220) ; v2(4270,3670) v2(4380,3670) ; v2(4365,2745) 4365,2680 C29.2@4427.6,2680 ; C20.2@4470,4052.4 v2(4470,4110) ; U12.5@4500,2352.64 4500,2162.4 4782.6,2162.4 4850,2095 v2(5015,2095) ; J8.MH1@4572.73,3035.83 4635,3035.83 4635,3043.7 J8.1@4678.35,3043.7 ; v2(4595,5180) U3.7@4595,5258.35 ; U13.2@4610,2070.75 4610,2162.4 ; C30.2@4704.06,2680 4704.06,2745 v2(4795,2745) R50.2@4795,2687.4 ; C10.2@4980,5187.4 v2(4980,5240) ; C34.2@5105,1767.6 5152.6,1767.6 5172,1787 5303,1787 5330,1760 5470,1760 v2(5470,1705) ; C76.2@5160,5192.4 v2(5160,5240) ; v2(5360,2485) 5390,2485 5410,2465 U15.25@5410,2406.73 ; U14.25@5410,2856.73 5410,2910 v2(5430,2930) ; U15.9@5460,2123.27 5460,2205 5495,2240 v2(5525,2240) ; U14.9@5460,2573.27 5460,2645 v2(5500,2685) ; v1(6020,5365) R19.2@6020,5422.6 ; v1(6045,1340) 6190.16,1340 J9.98@6190.16,1256.3 ; RA9.3@6080,5153 RA10.6@6080,5087 v1(6180,5087) ; J8.98@6190.16,3256.3 6190.16,3183 6250,3183 6250,3200 v1(6295,3200) ; J9.100@6221.65,1256.3 6265,1256.3 v1(6265,1280) ; J8.100@6221.65,3256.3 6265,3256.3 v1(6265,3230) ; C12.1@6280,5177.4 C13.1@6370,5177.4 C14.1@6460,5177.4 ; v1(6295,1310) 6344.38,1310 J9.MH4B@6344.38,1264.17 ; LED16.2@6777.4,3895 6777.4,4670 v1(6840,4670) ; RA23.8@7085,1402 7718,1402 7765,1355 7765,865 7688.19,788.19 SW17.4@7302.52,788.19 ; C35.2@7184.06,2275 7184.06,2205 7712.4,2205 R58.2@7712.4,2275 7770,2275 7770,2650 7470,2650 7470,2845 ; R49.1@7537.6,3075 7537.6,3010 7615.94,3010
  Top Layer w39.37: J1.5@1418.11,6070.08 1474.01,6125.98 J1.11@1691.93,6125.98 ; v2(2224,6240) v2(2224,6355) ; v1(2675,4475) 2725,4425 v2(2725,3910) ; HDR8.14@3850,700 4675,700 v2(4675,525) ; v1(4270,2745) v2(4365,2745) ; R80.1@4450,552.4 4450,700 ; v1(6256,2877) 6298,2835 6760,2835 7040,3115 7235,3115 7235,2845 7509.06,2845 C25.2@7509.06,2925 C26.2@7615.94,2925 7615.94,3010 7725,3010 C27.2@7725,3090.94 ; J8.MH3@6328.63,3035.83 6372.81,3080 6395,3080 6565,3250 6755,3250 6850,3345 6850,3640 7035,3825 7455,3825 7525,3755 7525,3695 7565,3655 v3(7635,3655) ; 6523.15,6086.61 J6.3@6573.15,6086.61 6623.15,6086.61 ; 6573.15,5997.24 J6.3B@6573.15,6047.24 ; J6.3A@6573.15,6125.98 6573.15,6175.98 ; 6659.41,5715 D7.1@6737.5,5715 ; 6680.63,6204.72 J6.2A@6730.63,6204.72 ; 6737.5,5602.85 D7.1@6737.5,5715 ; 6737.5,5817.38 D7.1@6737.5,5715 ; 6770,6154.72 J6.2@6770,6204.72 6770,6254.72 ; J6.2B@6809.37,6204.72 6859.37,6204.72 ; 6812.59,5715 D7.1@6737.5,5715 ; 7003.15,6086.61 J7.3@7053.15,6086.61 7103.15,6086.61 ; J7.3A@7053.15,6125.98 7053.15,6175.98 ; 7160.63,6204.72 J7.2A@7210.63,6204.72 ; 7250,6154.72 J7.2@7250,6204.72 7250,6254.72 ; J7.2B@7289.37,6204.72 7339.37,6204.72
  Top Layer w59.05: C23.2@7729.05,3810 7729.05,3940 C22.2@7730,3940.94
  Bottom Layer w7.87: v2(1069,5820) v2(1135,5820) ; HDR3.26@4650,5670 HDR3.25@4750,5670 HDR3.24@4850,5670 HDR3.23@4950,5670 HDR3.22@5050,5670 HDR3.21@5150,5670 HDR3.20@5250,5670 HDR3.19@5350,5670 ; S2.16@7007.72,1884.65 7107.72,1884.65 7207.72,1884.65 7407.72,1884.65 7507.72,1884.65 7607.72,1884.65 S2.9@7707.72,1884.65
  Bottom Layer w9.84: C64.2@5987.4,4145 6105,4145 v1(6145,4185)
  Bottom Layer w11.81: J3.8@3675.2,6050 3675.2,6100 3855.51,6100 J3.10@3855.51,6050
  Bottom Layer w19.68: HDR2.10@300,4750 HDR2.8@300,4850 HDR2.6@300,4950 HDR2.4@300,5050 HDR2.2@300,5150 HDR1.10@300,5550 375,5550 435,5610 435,6215 GJ1.2@470,6250 ; LCD1.1@390,4420 390,4560 v2(790,4560) ; v2(583,5928) 583,6000.91 J1.10@708.07,6125.98 ; v1(2085,4275) 2135,4275 2135,4450 ; J2.9@2295.72,6181.89 2342.61,6135 2375,6135 2404.77,6105.23 2404.77,6034.77 2385,6015 v2(2385,5690) ; 2385,5875 JP1.2@2850,5875 ; J2.11@2951.23,6124.98 3163.4,6124.98 J3.16@3238.39,6050 ; GJ2.1@3125,5180 GJ2.2@3225,5180 ; v1(3130,3605) v2(3260,3735) ; JP2.2@3625,5195 JP2.18@4425,5195 ; J3.8@3675.2,6050 J3.7@3585.04,6050 J3.6@3494.88,6050 J3.16@3238.39,6050 ; J3.10@3855.51,6050 J3.17@4222.24,6050 ; 3910.63,6050 J3.5@3910.63,5950 3910.63,5885.63 3875,5850 v1(3765,5850.39) v1(3625,5850) v2(3200,5850) 3200,6011.61 J3.16@3238.39,6050 ; J4.3@4572.05,6165.35 4626.69,6220 5117.4,6220 J5.3@5172.05,6165.35 ; 4980,5180 v2(4980,5240) ; C69.2@5012.6,3960 5012.6,3905 5220,3905 ; C67.2@5012.6,4050 5012.6,4195 5220,4195 ; C63.2@5012.6,4280 5012.6,4335 v1@5220,4335 ; C61.2@5012.6,4490 5012.6,4430 v1(5220,4430) ; C73.2@5155,3662.6 5220,3662.6 v1(5220,3870) ; 5160,5180 v2(5160,5240) ; 5380,3662.6 C71.2@5540,3662.6 ; 5425,4430 5425,4637.4 C58.2@5570,4637.4 ; v2(5430,2930) 5565,2795 5565,2705 5545,2685 v2(5500,2685) C74.2@5440,2685 ; v2(5470,1705) 5470,1750 5460,1760 5460,2240 v2(5525,2240) ; 5555,5070 v2(5555,5125) ; 5780,3870 5780,3662.6 C70.2@5845,3662.6 ; 5780,3910 5987.4,3910 C68.2@5987.4,3965 ; 5780,4200 5987.4,4200 C66.2@5987.4,4055 ; v1@5780,4325 5987.4,4325 C62.2@5987.4,4275 ; 5780,4420 5987.4,4420 C60.2@5987.4,4475 ; 5890,5070 v1(5890,5135) ; 6560,5068 v1(6560,5110) ; GJ4.1@6825,5450 GJ4.2@6925,5450 6925,5315 7150,5090 7429,5090 ; S2.13@7310,1885 v2(7310,2205) ; 7429,5325 7641,5325 7700,5266 HDR5.2@7700,5150 HDR5.4@7700,5050 HDR5.6@7700,4950 HDR5.8@7700,4850 HDR5.10@7700,4750 ; 7600,5326 HDR4.9@7600,5550
  Bottom Layer w39.37: 437,5928 v2(583,5928) ; GJ1.2@470,6250 470,6418 519,6467 6676,6467 6770,6373 J6.2@6770,6204.72 6770,6154.72 ; J1.10@708.07,6125.98 902.09,6320 1497.91,6320 J1.11@1691.93,6125.98 1685,6119.06 1685,5425.18 ; 1685,4725 1685,5434 ; J1.11@1692.93,6124.98 J2.10@1967.37,6124.98 ; J2.10@1967.37,6125.98 J2.10@1967.37,6210 ; J2.10@1967.37,6211.37 2058,6302 2774.21,6302 J2.11@2951.23,6124.98 ; SPKR1.2A@2010.24,5690.55 v2@2384.45,5690.55 ; v2(2224,6240) 2143,6159 2143,5981 2013.39,5851.39 2013.39,4705 v2(2135,4705) 2135,4450 2295,4450 ; v2(2224,6355) 2288,6419 6361,6419 6425,6355 6425,6120 6462.32,6082.68 J6.3@6573.15,6082.68 ; J2.9@2295.72,6181.89 2295.72,6302 ; v2(2725,3910) 2865,3910 ; J3.16@3238.39,6050 3498.39,6310 3962.24,6310 J3.17@4222.24,6050 4485.24,6312.99 J4.S@4700,6312.99 J5.S@5300,6312.99 ; JP2.2@3625,5195 v1(3625,5850) ; GJ5.1@3860,3875 GJ5.2@3960,3875 ; v1(4375,1295) v2(4375,1770) ; 4570,5180 5380,5180 5490,5070 7045,5070 7285,4830 C16.2@7285,4765 ; 4875,115 4875,182 4918,225 4962,225 5005,182 5005,115 ; 5395,3870 5395,3790 5380,3775 5380,2930 v2(5430,2930) ; v1(6045,1340) 6160,1455 6160,1900 6060,2000 6060,2400 6175,2515 6175,2820 6130,2865 6130,3230 v1(6265,3230) v1(6295,3200) ; 6275,115 6275,182 6318,225 6362,225 6405,182 6405,115 ; J9.MH3@6328.63,1035.83 6328.63,913.63 6295,880 6252,880 6120,1012 6120,1275 6260,1415 6260,1940 6160,2040 6160,2360 6275,2475 6275,2858 6190,2943 6190,3035.83 J8.MH3@6328.63,3035.83 ; J8.MH4B@6344.38,3264.17 6375,3233.56 6375,2435 6260,2320 6260,2080 6360,1980 6360,1375 6220,1235 6220,1130 6250,1100 6460,1100 6460,2020 6360,2120 6360,2280 6475,2395 v1(6475,3160) ; 6573.15,5997.24 J6.3B@6573.15,6047.24 ; J6.3@6573.15,6086.61 6623.15,6086.61 ; 7003.15,6086.61 J7.3@7053.15,6086.61 7103.15,6086.61 ; 7053.15,5997.24 J7.3B@7053.15,6047.24 ; 7250,6154.72 J7.2@7250,6204.72 7250,6254.72 ; J7.2B@7289.37,6204.72 7339.37,6204.72
  Bottom Layer w50: GJ7.1@3810,1155 GJ7.2@3910,1155 ; GJ3.1@4915,4920 GJ3.2@5015,4920 ; 5805,4370 6020,4370 6130,4480 6755,4480 7030,4205 7030,3840 7235,3840 C21.2@7235,3925
  Bottom Layer w59.05: HDR9.20@5950,350 6025,350 6025,115 ; HDR10.20@7350,350 7395,350 7430,315
  Bottom Layer w59.06: v2(4675,525) 4675,115 4875,115 ; 5005,115 6275,115 ; 6405,115 7370,115 7430,175 7430,315 7785,670 7785,1920 7635,2070 7635,4559 7429,4765 ; J6.3@6573.15,6082.68 6573.15,6204.72 J6.2@6770,6204.72 7053.15,6204.72 ; J7.3A@7053.15,6145.67 7053.15,6204.72 ; J7.2A@7210.63,6204.72 7053.15,6204.72 ; C16.2@7285,4765 7429,4765 ; C15.2@7285,5325 7429,5325 7429,4765 ; v1(5220,3870) 5780,3870 5780,4430 v1(5220,4430) v1(5220,3870)
  other v1: 175,647 4205,799.21 6460,1270 6185,1340 4375,1512 6375,2835 6475,2835 3540,3225 5965,3485 4475,3855 2900,3865 5580,4075 5790,4480 6300,4480 6265,4800 6230,4965 1010,5415 820,5645
  other v2: 4810,1852.11 4970,1915 4800,2145 4890,2745 2720,2910 6995,3225 3625,3310 3915,3315 3995,3315 3915,3665 3995,3665 2985,3950 5505,5255
GREEN0: J8.10 R12.1 | length 3497.1
  Top Layer w7.87: R12.1@3500,5562.6 3500,5505 3337,5342 3337,4933 3428,4842 3428,3822 3762,3488 4642,3488 4804.33,3325.67 J8.10@4804.33,3256.3
GREEN1: J8.12 R13.1 | length 3566.1
  Top Layer w7.87: R13.1@3590,5562.6 3590,5525 3568,5504 3524,5504 3353,5333 3353,4942 3444,4851 3444,3831 3771,3504 4661,3504 4835.83,3329.17 J8.12@4835.83,3256.3
GREEN#: D2.3 J3.2 R12.2 R13.2 | length 491.3
  Top Layer w7.87: R12.2@3499.9,5637.4 3589.9,5637.4 3589.9,5687.1 3570.31,5706.69 D2.3@3550,5706.69 3550,5866 3586,5902 3628,5902 3639,5913 J3.2@3639,5948.84
HDRIVE: D4.3 J3.13 J8.18 | length 4492.9
  Top Layer w7.87: J3.13@3730.32,6150 3742,6150 3811,6081 3811,6027 3775,5991 3775,5905 3833,5847 3833,5752 3855,5730 3855,5635 3813,5593 3813,5523 3746,5456 3551,5456 3401,5306 3401,4969 3492,4878 3492,3858 3798,3552 4703,3552 4930.31,3324.69 J8.18@4930.31,3256.3 ; 3855,5706.69 D4.3@3900,5706.69
INIT: R26.2 U5.8 U8.74 | length 1323.5
  Top Layer w7.87: U8.74@5824.8,4567.32 5824.8,4525.2 5835,4515 5985,4515 6188,4718 6488,4718 6523.98,4753.98 6523.98,4848.98 6547,4872 6628,4872 6730,4974 R26.2@6730,5100.2
IO0: HDR9.2 J9.7 | length 808.5
  Top Layer w7.87: J9.7@4772.83,1043.7 4772.83,627.17 HDR9.2@5050,350
IO1: HDR9.3 J9.9 | length 936.9
  Top Layer w7.87: J9.9@4804.33,1043.7 4804.33,665.67 5100,370 5100,300 HDR9.3@5150,250
IO2: HDR9.4 J9.11 | length 823.8
  Top Layer w7.87: J9.11@4835.83,1043.7 4835.83,664.17 HDR9.4@5150,350
IO3: HDR9.5 J9.13 | length 952.2
  Top Layer w7.87: J9.13@4867.32,1043.7 4867.32,702.68 5200,370 5200,300 HDR9.5@5250,250
IO4: HDR9.6 J9.15 | length 839.2
  Top Layer w7.87: J9.15@4898.82,1043.7 4898.82,701.18 HDR9.6@5250,350
IO5: HDR9.7 J9.17 | length 967.5
  Top Layer w7.87: J9.17@4930.31,1043.7 4930.31,739.69 5300,370 5300,300 HDR9.7@5350,250
IO6: HDR9.8 J9.19 | length 854.5
  Top Layer w7.87: J9.19@4961.81,1043.7 4961.81,738.19 HDR9.8@5350,350
IO7: HDR9.9 J9.21 | length 982.9
  Top Layer w7.87: J9.21@4993.31,1043.7 4993.31,776.69 5400,370 5400,300 HDR9.9@5450,250
IO8: HDR9.10 J9.23 | length 869.8
  Top Layer w7.87: J9.23@5024.8,1043.7 5024.8,775.2 HDR9.10@5450,350
IO9: HDR9.11 J9.25 | length 998.2
  Top Layer w7.87: J9.25@5056.3,1043.7 5056.3,813.7 5500,370 5500,300 HDR9.11@5550,250
IO10: HDR9.12 J9.27 | length 885.2
  Top Layer w7.87: J9.27@5087.79,1043.7 5087.79,812.21 HDR9.12@5550,350
IO11: HDR9.13 J9.29 | length 1013.5
  Top Layer w7.87: J9.29@5119.29,1043.7 5119.29,850.71 5600,370 5600,300 HDR9.13@5650,250
IO12: HDR9.14 J9.31 | length 900.5
  Top Layer w7.87: J9.31@5150.79,1043.7 5150.79,849.21 HDR9.14@5650,350
IO13: HDR9.15 J9.33 | length 1028.9
  Top Layer w7.87: J9.33@5182.28,1043.7 5182.28,887.72 5700,370 5700,300 HDR9.15@5750,250
IO14: HDR9.16 J9.35 | length 915.8
  Top Layer w7.87: J9.35@5213.78,1043.7 5213.78,886.22 HDR9.16@5750,350
IO15: HDR9.17 J9.37 | length 1044.2
  Top Layer w7.87: J9.37@5245.28,1043.7 5245.28,924.72 5800,370 5800,300 HDR9.17@5850,250
IO16: HDR9.18 J9.39 | length 931.1
  Top Layer w7.87: J9.39@5276.77,1043.7 5276.77,923.23 HDR9.18@5850,350
IO17: HDR9.19 J9.41 | length 1059.5
  Top Layer w7.87: J9.41@5308.27,1043.7 5308.27,961.73 5900,370 5900,300 HDR9.19@5950,250
IO18: HDR10.2 J9.43 | length 1446.5
  Top Layer w7.87: J9.43@5339.76,1043.7 5339.76,960.24 5892,408 6392,408 HDR10.2@6450,350
IO19: HDR10.3 J9.45 | length 1601.2
  Top Layer w7.87: J9.45@5371.26,1043.7 5371.26,953.74 5901,424 6446,424 6500,370 6500,300 HDR10.3@6550,250
IO20: HDR10.4 J9.47 | length 1491.1
  Top Layer w7.87: J9.47@5402.76,1043.7 5402.76,947.24 5910,440 6460,440 HDR10.4@6550,350
IO21: HDR10.5 J9.49 | length 1645.8
  Top Layer w7.87: J9.49@5434.25,1043.7 5434.25,940.75 5919,456 6514,456 6600,370 6600,300 HDR10.5@6650,250
IO22: HDR10.6 J9.51 | length 1535.7
  Top Layer w7.87: J9.51@5465.75,1043.7 5465.75,934.25 5928,472 6528,472 HDR10.6@6650,350
IO23: HDR10.7 J9.53 | length 1690.4
  Top Layer w7.87: J9.53@5497.24,1043.7 5497.24,927.76 5937,488 6582,488 6700,370 6700,300 HDR10.7@6750,250
IO24: HDR10.8 J9.55 | length 1580.3
  Top Layer w7.87: J9.55@5528.74,1043.7 5528.74,921.26 5946,504 6596,504 HDR10.8@6750,350
IO25: HDR10.9 J9.57 | length 1735.1
  Top Layer w7.87: J9.57@5560.24,1043.7 5560.24,914.76 5955,520 6650,520 6800,370 6800,300 HDR10.9@6850,250
IO26: HDR10.10 J9.59 | length 1624.9
  Top Layer w7.87: J9.59@5591.73,1043.7 5591.73,908.27 5964,536 6664,536 HDR10.10@6850,350
IO27: HDR10.11 J9.61 | length 1779.7
  Top Layer w7.87: J9.61@5623.23,1043.7 5623.23,901.77 5973,552 6718,552 6900,370 6900,300 HDR10.11@6950,250
IO28: HDR10.12 J9.63 | length 1669.6
  Top Layer w7.87: J9.63@5654.72,1043.7 5654.72,895.28 5982,568 6732,568 HDR10.12@6950,350
IO29: HDR10.13 J9.65 | length 1824.3
  Top Layer w7.87: J9.65@5686.22,1043.7 5686.22,888.78 5991,584 6786,584 7000,370 7000,300 HDR10.13@7050,250
IO30: HDR10.14 J9.67 | length 1714.2
  Top Layer w7.87: J9.67@5717.72,1043.7 5717.72,882.28 6000,600 6800,600 HDR10.14@7050,350
IO31: HDR10.15 J9.69 | length 1868.9
  Top Layer w7.87: J9.69@5749.21,1043.7 5749.21,875.79 6009,616 6854,616 7100,370 7100,300 HDR10.15@7150,250
IO32: HDR10.16 J9.71 | length 1758.8
  Top Layer w7.87: J9.71@5780.71,1043.7 5780.71,869.29 6018,632 6868,632 HDR10.16@7150,350
IO33: HDR10.17 J9.73 | length 1913.5
  Top Layer w7.87: J9.73@5812.21,1043.7 5812.2,862.79 6027,648 6922,648 7200,370 7200,300 HDR10.17@7250,250
IO34: HDR10.18 J9.75 | length 1803.4
  Top Layer w7.87: J9.75@5843.7,1043.7 5843.7,856.3 6036,664 6936,664 HDR10.18@7250,350
IO35: HDR10.19 J9.77 | length 1958.2
  Top Layer w7.87: J9.77@5875.2,1043.7 5875.2,849.8 6045,680 6990,680 7300,370 7300,300 HDR10.19@7350,250
JIOA0: J8.3 R45.1 RA19.5 RA20.4 | length 1295.1
  Top Layer w7.87: R45.1@3640,3122.4 3640,3155 3650,3165 3953,3165 3965,3153 RA19.5@3965,3122 3998,3122 4040,3080 4170,3080 4215,3035 RA20.4@4215,2998 4252,2998 4280,2970 4700,2970 4709.84,2979.84 J8.3@4709.84,3043.7
JIOA0#: HDR2.1 RA20.5 | length 5344.2
  Top Layer w7.87: HDR2.1@200,5150 200,5100 320,5100 350,5070 350,5010 428,4932 2598,4932 2950,4580 2950,3938 3618,3270 4150,3270 4215,3205 RA20.5@4215,3122
JIOA1: J8.5 RA19.6 RA20.3 | length 1029.4
  Top Layer w7.87: RA19.6@3915,3122 3915,3090 3925,3080 4010,3080 4030,3060 4140,3060 4165,3035 4165,2965 4176,2954 4714,2954 4741.34,2981.34 J8.5@4741.34,3043.7
JIOA1#: HDR2.3 RA20.6 | length 5187.7
  Top Layer w7.87: HDR2.3@200,5050 242,5008 327,5008 419,4916 2589,4916 2934,4571 2934,3930 3610,3254 4116,3254 4165,3205 RA20.6@4165,3122
JIOA2: J8.7 RA19.7 RA20.2 | length 1123.2
  Top Layer w7.87: RA19.7@3865,3122 3865,3085 3890,3060 4000,3060 4020,3040 4105,3040 4115,3030 4115,2965 4142,2938 4728,2938 4772.83,2982.83 J8.7@4772.83,3043.7
JIOA2#: HDR2.5 RA20.7 | length 5093.9
  Top Layer w7.87: HDR2.5@200,4950 250,4900 2580,4900 2918,4562 2918,3920 3600,3238 4077,3238 4115,3200 RA20.7@4115,3122
JIOA3: J8.9 RA20.1 | length 881.2
  Top Layer w7.87: RA20.1@4065,2998 4065,2960 4103,2922 4747,2922 4804.33,2979.33 J8.9@4804.33,3043.7
JIOA3#: HDR2.7 RA20.8 | length 5059.8
  Top Layer w7.87: HDR2.7@200,4850 250,4800 310,4800 394,4884 2571,4884 2902,4553 2902,3912 3592,3222 4023,3222 4065,3180 RA20.8@4065,3122
JIOB0: J8.83 RA17.1 | length 766.5
  Top Layer w7.87: J8.83@5969.69,3043.7 5969.69,3109.69 6021,3161 6331,3161 6398,3228 6398,3322 6330,3390 RA17.1@6330,3423
JIOB0#: HDR5.1 RA17.8 | length 2486.4
  Top Layer w7.87: RA17.8@6330,3547 6330,3580 6572,3822 6882,3822 6972,3912 6972,4602 7018,4648 7278,4648 7528,4898 7528,5118 7560,5150 HDR5.1@7600,5150
JIOB1: J8.85 RA17.2 | length 740.1
  Top Layer w7.87: J8.85@6001.18,3043.7 6001.18,3106.18 6040,3145 6340,3145 6414,3219 6414,3356 6380,3390 RA17.2@6380,3423
JIOB1#: HDR5.3 RA17.7 | length 2342.2
  Top Layer w7.87: RA17.7@6380,3547 6380,3605 6581,3806 6891,3806 6988,3903 6988,4593 7027,4632 7287,4632 7544,4889 7544,4994 HDR5.3@7600,5050
JIOB2: J8.87 RA17.3 | length 716.7
  Top Layer w7.87: J8.87@6032.68,3043.7 6032.68,3107.68 6054,3129 6349,3129 6430,3210 RA17.3@6430,3423
JIOB2#: HDR5.5 RA17.6 | length 2221.5
  Top Layer w7.87: RA17.6@6430,3547 6430,3630 6590,3790 6900,3790 7004,3894 7004,4584 7036,4616 7296,4616 7560,4880 7560,4910 HDR5.5@7600,4950
JIOB3: J8.89 RA17.4 | length 717.9
  Top Layer w7.87: J8.89@6064.17,3043.7 6064.17,3103.17 6074,3113 6358,3113 6446,3201 6446,3356 6480,3390 RA17.4@6480,3423
JIOB3#: HDR5.7 RA17.5 | length 2127.2
  Top Layer w7.87: RA17.5@6480,3547 6480,3655 6599,3774 6909,3774 7020,3885 7020,4575 7045,4600 7305,4600 7555,4850 HDR5.7@7600,4850
JTAG_CNCT_A: R70.1 RA25.2 U8.106 | length 8488.7
  Top Layer w7.87: R70.1@275,447.4 275,555 265,565 160,565 145,580 145,680 185,720 v1(390,720) ; v2(3705,4355) 3744,4394 3804,4394 3920,4510 4795,4510 4870,4585 5015,4585 5058,4628 5177,4628 5194.88,4610.12 U8.106@5194.88,4567.32
  Bottom Layer w7.87: v1(390,720) 390,870 373,887 373,3078 953,3658 2738,3658 3270,4190 3540,4190 v2(3705,4355)
JTAG_CNCT_A#: HDR6.10 R70.2 | length 383.4
  Top Layer w7.87: R70.2@347.4,445 385,445 580,250 HDR6.10@650,250
JTAG_CNCT_B: R69.1 RA25.1 U8.131 | length 8932.3
  Top Layer w7.87: RA25.1@225,523 125,523 125,685 176,736 301,736 405,840 v1(940,840) ; v2(3975,4040) 3998,4063 3998,4263 4037,4302 4748,4302 4806,4244 4806,4054 4825,4035 4875,4035 4901.42,4061.42 U8.131@5082.68,4061.42
  Bottom Layer w7.87: v1(940,840) 914,866 719,866 581,1004 581,2961 1070,3450 2855,3450 3387,3982 3917,3982 v2(3975,4040)
JTAG_CNCT_B#: HDR7.10 R69.2 | length 1589.7
  Top Layer w7.87: R69.2@125,447.6 177.4,447.6 240,385 345,385 580,150 1450,150 HDR7.10@1550,250
KBCLOCK: J4.5 J8.22 RA2.1 | length 4820.3
  Top Layer w7.87: J4.5@4572.05,6066.93 4409,5903.88 4409,5774 4401.57,5766.57 4266.57,5766.57 4225,5725 RA2.1@4225,5678 4183,5678 4155,5650 3920,5650 3845,5575 3845,5505 3764,5424 3569,5424 3433,5288 3433,4987 3524,4896 3524,3876 3816,3584 4731,3584 4993.31,3321.69 J8.22@4993.31,3256.3
KBDATA: J4.1 J8.24 RA2.2 | length 5003.6
  Top Layer w7.87: J4.1@4650.79,6165.35 4617,6131.57 4617,6046 4594,6023 4553.39,6023 4424.75,5894.36 4424.75,5763.75 4411.82,5750.82 4295.82,5750.82 4275,5730 RA2.2@4275,5678 4275,5645 4264,5634 3929,5634 3861,5566 3861,5496 3773,5408 3578,5408 3449,5279 3449,4996 3540,4905 3540,3885 3825,3600 4750,3600 5024.8,3325.2 J8.24@5024.8,3256.3
LCD_BCKL: J9.22 R35.1 | length 5212.7
  Top Layer w7.87: v2(1905,3800) 1935,3800 4192,1543 4805,1543 4993.31,1354.69 J9.22@4993.31,1256.3 ; R35.1@2300,4587.6 2300,4555 2315,4540 v2(2350,4540)
  Bottom Layer w7.87: v2(1905,3800) 2350,4245 v2(2350,4540)
LCD_D0: LCD1.7 RA11.1 U17.9 | length 5899.2
  Top Layer w7.87: RA11.1@1065,4573 1065,4540 990,4465 LCD1.7@990,4420 1140,4270 1590,4270 4237,1623 4883.81,1623 4979.81,1527 5287,1527 5409.57,1649.57 U17.9@5409.57,1696.06
LCD_D1: LCD1.8 RA11.2 U17.8 | length 5740
  Top Layer w7.87: RA11.2@1115,4573 1115,4500 1090,4475 LCD1.8@1090,4420 1220,4290 1595,4290 4246,1639 4890.08,1639 4986.08,1543 5278,1543 5383.98,1648.98 U17.8@5383.98,1696.06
